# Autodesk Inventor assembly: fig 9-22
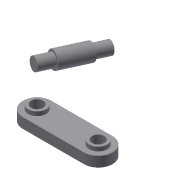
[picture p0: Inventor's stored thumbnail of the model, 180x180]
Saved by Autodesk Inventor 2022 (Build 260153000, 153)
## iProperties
Created: 2002-01
Part Number: fig 9-22
Document SubType Name: Assembly
Designer: ***
Control State: 0
Master: False
Checked Out: False
Shininess: 64.0
Length Units: 11269
Angle Units: 11279
Time Units: 11290
Mass Units: 11283
Length Display Precision: 3
Angle Display Precision: 2
Density: 0.0
Volumn: 0.0
Area: 0.0
PropertySet Name: Model Information
Author: ***
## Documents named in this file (3)
- D:\PROJECTS_2021\Resources\Part Files\c09_Inv_2022_prt\fig 9-22.iam
- D:\PROJECTS_2021\Resources\Part Files\c09_Inv_2022_prt\Part5.ipt
- D:\PROJECTS_2021\Resources\Part Files\c09_Inv_2022_prt\Part6.ipt
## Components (2 placed, 2 different names)
1. Part5:1
2. Part6:1
